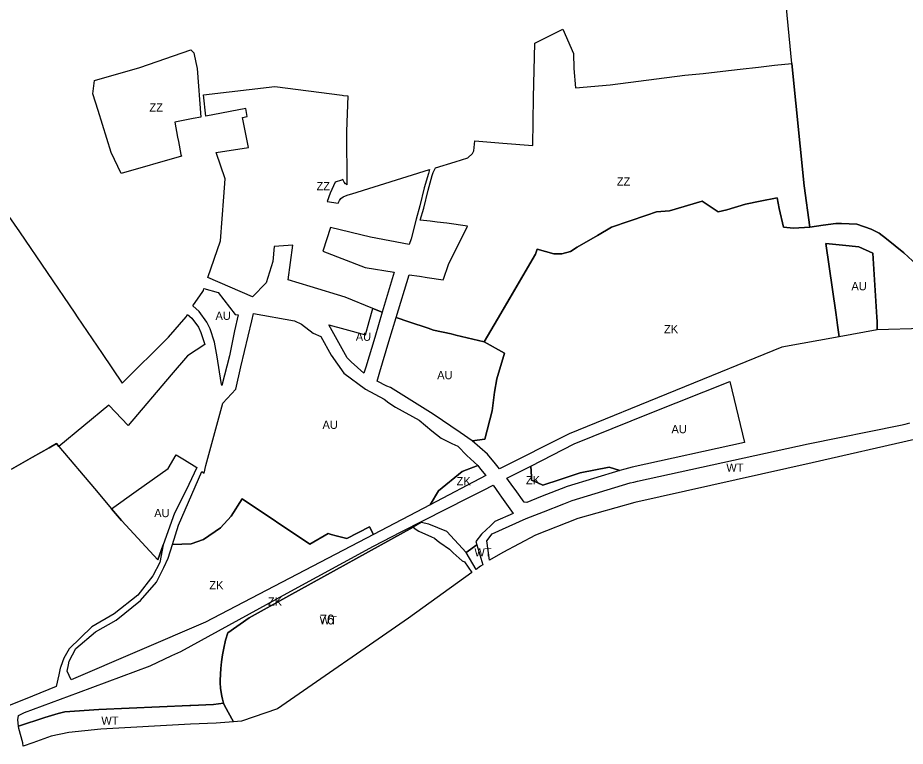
# Model space of a CAD drawing. Extents: x -535894 to -532834, y -1165802 to -1163647.
# Drawn here: x -534886 to -534347, y -1165569 to -1165127 of the extents above; entities that cross this region are included whole.
import ezdxf

# ---------------------------------------------------------------- set-up
doc = ezdxf.new("R2010")
doc.units = 0
for name, color, linetype in [('Vrstva 10', 7, 'Continuous'), ('Vrstva 16', 7, 'Continuous'), ('Vrstva 22', 7, 'Continuous'), ('Vrstva 4', 7, 'Continuous'), ('Vrstva 5', 7, 'Continuous'), ('Vrstva 61', 7, 'Continuous')]:
    doc.layers.add(name, color=color, linetype=linetype)

msp = doc.modelspace()

# ---------------------------------------------------------------- linework, layer by layer
at = {"layer": 'Vrstva 10'}
for points in [[(-534656.466, -1165308.487), (-534648.661, -1165282.513), (-534642.27, -1165283.46), (-534637.76, -1165284.12), (-534627.97, -1165285.63), (-534627.83, -1165285.22), (-534624.62, -1165276.23), (-534613.26, -1165253.08), (-534625.77, -1165251.25), (-534631.5, -1165250.59), (-534635.8, -1165250.1), (-534641.82, -1165249.4), (-534639.72, -1165242.1), (-534636.98, -1165231.14), (-534634.63, -1165222.23), (-534633.92, -1165220.53), (-534632.69, -1165217.6), (-534620.573, -1165213.915), (-534613.071, -1165211.633), (-534610.136, -1165208.971), (-534609.411, -1165207.236), (-534608.72, -1165201.29), (-534591.748, -1165202.638), (-534573.555, -1165204.082), (-534573.16, -1165174.91), (-534572.34, -1165142), (-534555.22, -1165133.48), (-534548.9, -1165148.28), (-534548.58, -1165157.34), (-534547.592, -1165169.021), (-534526.56, -1165167.24), (-534481.169, -1165161.423), (-534470.12, -1165160.31), (-534458.2, -1165158.95), (-534447.57, -1165157.79), (-534436.45, -1165156.54), (-534426.83, -1165155.34), (-534416.26, -1165154.3), (-534408.79, -1165228.57), (-534405.45, -1165253.73), (-534415.33, -1165254.24), (-534421.35, -1165253.74), (-534423.92, -1165242.4), (-534425.2, -1165235.77), (-534435.5, -1165237.88), (-534444.47, -1165239.8), (-534455.8, -1165243.06), (-534461.02, -1165244.38), (-534470.72, -1165237.94), (-534490.64, -1165243.85), (-534498.4, -1165244.45), (-534504.24, -1165246.32), (-534515.07, -1165249.99), (-534525.69, -1165253.61), (-534534.27, -1165258.67), (-534546.51, -1165265.89), (-534550.66, -1165268.35), (-534556, -1165269.92), (-534560.78, -1165269.82), (-534570.97, -1165266.95), (-534571.87, -1165270.05), (-534586.042, -1165294.326), (-534594.9, -1165309.5), (-534602.97, -1165323.34), (-534620.31, -1165319.14), (-534623.17, -1165318.51), (-534633.83, -1165316.18), (-534637.1, -1165315.06), (-534648.89, -1165311.07)], [(-534781.076, -1165145.96), (-534779.24, -1165147.77), (-534778.072, -1165153.706), (-534777.364, -1165157.303), (-534774.981, -1165186.877), (-534779.72, -1165187.79), (-534790.92, -1165189.96), (-534789.14, -1165199.14), (-534788.65, -1165201.64), (-534787.13, -1165209.49), (-534786.835, -1165210.52), (-534823.49, -1165221.01), (-534829.46, -1165208.31), (-534837.43, -1165182.94), (-534840.66, -1165172.65), (-534839.59, -1165164.67), (-534812.16, -1165156.7)], [(-534770.876, -1165284.164), (-534763.18, -1165261.89), (-534761.05, -1165235.16), (-534760.2, -1165224.39), (-534765.68, -1165208.38), (-534746.16, -1165205.31), (-534749.82, -1165187.09), (-534746.85, -1165186.52), (-534747.79, -1165181.61), (-534772.09, -1165186.32), (-534773.45, -1165173.38), (-534730.12, -1165168.22), (-534689.23, -1165173.62), (-534688.37, -1165173.69), (-534685.89, -1165173.92), (-534686.67, -1165195.7), (-534686.326, -1165227.952), (-534687.132, -1165227.394), (-534687.28, -1165227.291), (-534688.098, -1165226.32), (-534688.823, -1165224.816), (-534689.62, -1165225.087), (-534693.462, -1165226.393), (-534696.454, -1165232.948), (-534698.451, -1165238.101), (-534691.61, -1165239), (-534690.956, -1165237.548), (-534689.975, -1165236.279), (-534688.724, -1165235.276), (-534687.313, -1165234.607), (-534685.716, -1165234.065), (-534683.404, -1165233.352), (-534636.153, -1165218.674), (-534636.93, -1165221.04), (-534639.56, -1165229.81), (-534642.21, -1165240.82), (-534644.287, -1165248.754), (-534647.4, -1165260.65), (-534648.68, -1165264.17), (-534671.96, -1165259.81), (-534696.376, -1165253.853), (-534700.96, -1165268.14), (-534675.39, -1165278.09), (-534657.628, -1165281.081), (-534664.905, -1165305.299), (-534670.68, -1165302.976), (-534687.53, -1165296.2), (-534708.76, -1165289.69), (-534722.11, -1165285.6), (-534719.29, -1165264.53), (-534730.57, -1165265.33), (-534731.26, -1165274.58), (-534735.39, -1165287.4), (-534743.59, -1165295.91)]]:
    msp.add_lwpolyline(points, close=True, dxfattribs=at)
at = {"layer": 'Vrstva 16'}
for points in [[(-534336.76, -1165315.12), (-534364.57, -1165315.97), (-534364.596, -1165310.9), (-534364.61, -1165308.23), (-534367.17, -1165269.4), (-534375.67, -1165265.6), (-534385.585, -1165264.585), (-534395.69, -1165263.55), (-534389.63, -1165305.51), (-534388.99, -1165309.98), (-534388.62, -1165313.06), (-534387.514, -1165320.16), (-534422.4, -1165326.53), (-534551.38, -1165379.05), (-534593.742, -1165400.311), (-534597.026, -1165396.305), (-534598.221, -1165394.846), (-534601.042, -1165391.405), (-534610.247, -1165383.446), (-534602.56, -1165382.4), (-534598.25, -1165365.19), (-534596.74, -1165353.72), (-534595.37, -1165345.7), (-534590.76, -1165330.1), (-534602.97, -1165323.34), (-534594.9, -1165309.5), (-534571.87, -1165270.05), (-534570.97, -1165266.95), (-534560.78, -1165269.82), (-534556, -1165269.92), (-534550.66, -1165268.35), (-534546.51, -1165265.89), (-534534.27, -1165258.67), (-534525.69, -1165253.61), (-534515.07, -1165249.99), (-534504.24, -1165246.32), (-534498.4, -1165244.45), (-534490.64, -1165243.85), (-534470.72, -1165237.94), (-534461.02, -1165244.38), (-534455.8, -1165243.06), (-534444.47, -1165239.8), (-534435.5, -1165237.88), (-534425.2, -1165235.77), (-534423.92, -1165242.4), (-534421.35, -1165253.74), (-534415.33, -1165254.24), (-534405.45, -1165253.73), (-534397.29, -1165252.4), (-534389.65, -1165251.4), (-534386.06, -1165251.44), (-534376.79, -1165251.88), (-534368.13, -1165254.92), (-534363.2, -1165257.26), (-534358.8, -1165260.74), (-534348.28, -1165269.23), (-534340.36, -1165276.59)], [(-534889.94, -1165400.51), (-534885.71, -1165398.12), (-534877.22, -1165393.33), (-534867.2, -1165387.69), (-534862.73, -1165385.01), (-534861.21, -1165386.81), (-534839.653, -1165412.241), (-534829.214, -1165424.557), (-534823.21, -1165431.64), (-534822.96, -1165431.91), (-534801.16, -1165455.68), (-534797.86, -1165446.44), (-534800.02, -1165457.14), (-534804.19, -1165465.36), (-534813.3, -1165476.94), (-534827.72, -1165488.42), (-534841.13, -1165496.3), (-534854.91, -1165509.61), (-534858.15, -1165515.35), (-534858.97, -1165517.45), (-534860.3, -1165520.88), (-534860.51, -1165521.43), (-534861.32, -1165525.37), (-534862.8, -1165532.4), (-534877.24, -1165538.36), (-534912.68, -1165552.42)]]:
    msp.add_lwpolyline(points, dxfattribs=at)
for points in [[(-534607.004, -1165398.328), (-534605.192, -1165400.539), (-534601.98, -1165404.458), (-534635.941, -1165422.215), (-534630.7, -1165413.78), (-534616.38, -1165402.05)], [(-534520.704, -1165401.395), (-534552.702, -1165410.995), (-534568.837, -1165417.43), (-534577.132, -1165420.742), (-534578.843, -1165420.532), (-534584.327, -1165412.961), (-534585.708, -1165411.053), (-534589.332, -1165406.049), (-534574.828, -1165398.663), (-534574.43, -1165404.96), (-534574.28, -1165407.33), (-534570.57, -1165408.93), (-534567.43, -1165410.29), (-534557.01, -1165406.86), (-534544.87, -1165402.87), (-534527.22, -1165399.28)], [(-534625.805, -1165438.391), (-534636.67, -1165433.924), (-534641.319, -1165433.008), (-534646.155, -1165435.684), (-534721.707, -1165477.481), (-534745.62, -1165490.71), (-534758.745, -1165499.805), (-534759.99, -1165504.33), (-534761.08, -1165509.14), (-534761.82, -1165513.22), (-534762.44, -1165517.45), (-534762.85, -1165521.52), (-534763.11, -1165525.02), (-534763.25, -1165528.91), (-534763.26, -1165530.29), (-534763.09, -1165533.48), (-534762.76, -1165536.1), (-534762.37, -1165538.34), (-534761.95, -1165540.22), (-534761.238, -1165542.687), (-534767.34, -1165543.34), (-534781.05, -1165543.94), (-534781.63, -1165543.97), (-534836.88, -1165546.52), (-534857.57, -1165547.81), (-534861.62, -1165548.94), (-534869.82, -1165551.23), (-534885.69, -1165556.54), (-534886.11, -1165552.64), (-534885.76, -1165550.05), (-534882.03, -1165548.34), (-534849.32, -1165536.17), (-534805.71, -1165519.94), (-534792.57, -1165513.75), (-534787.1, -1165511.18), (-534722.56, -1165475.88), (-534670.22, -1165447.23), (-534653.44, -1165438.69), (-534612.41, -1165417.8), (-534603.53, -1165413.28), (-534597.581, -1165410.25), (-534593.887, -1165415.471), (-534592.444, -1165417.51), (-534585.468, -1165427.37), (-534596.584, -1165432.419), (-534599.518, -1165435.213), (-534601.568, -1165437.166), (-534604.649, -1165440.099), (-534608.122, -1165444.506), (-534607.549, -1165446.401), (-534614.062, -1165451.061)], [(-534792.243, -1165446.224), (-534780.95, -1165445.79), (-534773.45, -1165443.33), (-534763.2, -1165436.26), (-534756.71, -1165429.04), (-534749.861, -1165418.525), (-534708.8, -1165446.03), (-534697.82, -1165439.67), (-534696.005, -1165440.161), (-534692.969, -1165440.982), (-534686.509, -1165442.728), (-534672.71, -1165435.57), (-534670.299, -1165440.18), (-534772.12, -1165493.42), (-534853.75, -1165528.43), (-534856.09, -1165523.12), (-534855.37, -1165519.3), (-534854.95, -1165517.06), (-534850.87, -1165509.4), (-534839.06, -1165499.27), (-534826.42, -1165492.24), (-534811.76, -1165480.33), (-534801.92, -1165469.07), (-534797.58, -1165460.25), (-534794.8, -1165454.57)]]:
    msp.add_lwpolyline(points, close=True, dxfattribs=at)
at = {"layer": 'Vrstva 22'}
for points in [[(-534340.36, -1165276.59), (-534348.28, -1165269.23), (-534358.8, -1165260.74), (-534363.2, -1165257.26), (-534368.13, -1165254.92), (-534376.79, -1165251.88), (-534386.06, -1165251.44), (-534389.65, -1165251.4), (-534397.29, -1165252.4), (-534405.45, -1165253.73), (-534408.79, -1165228.57), (-534416.26, -1165154.3), (-534420.23, -1165114.18), (-534421.45, -1165101.43), (-534422.065, -1165096.672), (-534422.065, -1165096.672), (-534403.258, -1165095.841), (-534381.169, -1165094.484), (-534372.898, -1165093.976), (-534362.94, -1165093.25), (-534340.945, -1165094.96)], [(-534899.65, -1165235.85), (-534885.09, -1165256.54), (-534851.51, -1165305.91), (-534850.05, -1165308.06), (-534834.92, -1165330.4), (-534822.71, -1165348.42), (-534794.69, -1165320.4), (-534784.03, -1165308.09), (-534783.149, -1165306.655), (-534780.557, -1165308.993), (-534776.549, -1165314.45), (-534774.961, -1165317.626), (-534772.56, -1165324.913), (-534783.217, -1165331.674), (-534793.03, -1165343.33), (-534819.26, -1165374.14), (-534830.8, -1165361.69), (-534861.21, -1165386.81), (-534862.73, -1165385.01), (-534867.2, -1165387.69), (-534877.22, -1165393.33), (-534885.71, -1165398.12), (-534889.94, -1165400.51)]]:
    msp.add_lwpolyline(points, dxfattribs=at)
for points in [[(-534364.57, -1165315.97), (-534387.514, -1165320.16), (-534388.62, -1165313.06), (-534388.99, -1165309.98), (-534389.63, -1165305.51), (-534395.69, -1165263.55), (-534385.585, -1165264.585), (-534375.67, -1165265.6), (-534367.17, -1165269.4), (-534364.61, -1165308.23), (-534364.596, -1165310.9)], [(-534762.608, -1165347.87), (-534765.202, -1165332.461), (-534766.72, -1165323.467), (-534769.399, -1165315.334), (-534771.411, -1165311.31), (-534776.083, -1165304.947), (-534779.821, -1165301.364), (-534779.49, -1165300.88), (-534774.33, -1165293.32), (-534773.48, -1165292.09), (-534773.21, -1165290.92), (-534764.53, -1165293.41), (-534754.18, -1165306.73), (-534752.459, -1165306.87), (-534754.687, -1165316.58), (-534757.69, -1165331.84), (-534762.293, -1165349.741)], [(-534607.004, -1165398.328), (-534616.38, -1165402.05), (-534630.7, -1165413.78), (-534635.941, -1165422.215), (-534670.299, -1165440.18), (-534672.71, -1165435.57), (-534686.509, -1165442.728), (-534692.969, -1165440.982), (-534696.005, -1165440.161), (-534697.82, -1165439.67), (-534708.8, -1165446.03), (-534749.861, -1165418.525), (-534756.71, -1165429.04), (-534763.2, -1165436.26), (-534773.45, -1165443.33), (-534780.95, -1165445.79), (-534792.243, -1165446.224), (-534788.69, -1165434.63), (-534774.44, -1165402.06), (-534773.095, -1165402.961), (-534772.095, -1165398.401), (-534761.79, -1165360.41), (-534753.851, -1165351.984), (-534750.684, -1165338.491), (-534744.129, -1165310.569), (-534743.052, -1165305.979), (-534718.125, -1165310.44), (-534714.037, -1165312.461), (-534706.875, -1165318.091), (-534702.167, -1165320.064), (-534695.88, -1165331.28), (-534688.17, -1165342.38), (-534675.04, -1165351.98), (-534663.67, -1165357.97), (-534660.93, -1165360.38), (-534656.806, -1165362.855), (-534642.55, -1165370.754), (-534634.894, -1165377.362), (-534629.25, -1165381.75), (-534622.61, -1165384.94), (-534619.01, -1165386.65), (-534613.509, -1165392.332)], [(-534670.68, -1165302.976), (-534664.905, -1165305.299), (-534669.517, -1165320.647), (-534674.897, -1165338.553), (-534676.018, -1165342.285), (-534683.831, -1165335.456), (-534686.218, -1165332.95), (-534697.266, -1165312.904), (-534687.7, -1165315.57), (-534675.18, -1165319.07), (-534672.89, -1165310.88)], [(-534602.97, -1165323.34), (-534590.76, -1165330.1), (-534595.37, -1165345.7), (-534596.74, -1165353.72), (-534598.25, -1165365.19), (-534602.56, -1165382.4), (-534610.247, -1165383.446), (-534617.669, -1165378.227), (-534633.99, -1165367.14), (-534659.903, -1165351.067), (-534662.084, -1165350.114), (-534668.097, -1165347.197), (-534666.386, -1165341.503), (-534660.844, -1165323.061), (-534656.466, -1165308.487), (-534648.89, -1165311.07), (-534637.1, -1165315.06), (-534633.83, -1165316.18), (-534623.17, -1165318.51), (-534620.31, -1165319.14)], [(-534544.87, -1165402.87), (-534557.01, -1165406.86), (-534567.43, -1165410.29), (-534570.57, -1165408.93), (-534574.28, -1165407.33), (-534574.43, -1165404.96), (-534574.828, -1165398.663), (-534548.51, -1165385.26), (-534502.24, -1165366.65), (-534454.003, -1165347.255), (-534444.988, -1165384.388), (-534513.151, -1165399.411), (-534517.583, -1165400.459), (-534520.704, -1165401.395), (-534527.22, -1165399.28)], [(-534829.214, -1165424.557), (-534814.32, -1165413.92), (-534794.94, -1165400.08), (-534790.12, -1165391.9), (-534784.89, -1165394.84), (-534777.48, -1165399.64), (-534783.92, -1165413.27), (-534791.04, -1165427.36), (-534797.86, -1165446.44), (-534801.16, -1165455.68), (-534822.96, -1165431.91), (-534823.21, -1165431.64)]]:
    msp.add_lwpolyline(points, close=True, dxfattribs=at)
at = {"layer": 'Vrstva 4'}
msp.add_lwpolyline([(-534341.94, -1165382.62), (-534404.04, -1165396.72), (-534511.63, -1165420.88), (-534546.3, -1165430.52), (-534571.82, -1165440.57), (-534591.82, -1165451.2), (-534599.87, -1165455.71), (-534601.363, -1165444.1), (-534598.29, -1165439.76), (-534577.5, -1165430.58), (-534567.01, -1165426.39), (-534554.75, -1165421.51), (-534549.73, -1165419.5), (-534514.4, -1165408.9), (-534512.18, -1165408.41), (-534509.97, -1165407.93), (-534406.37, -1165385.09), (-534350.42, -1165373.76), (-534347.57, -1165373.21), (-534344.67, -1165372.49)], dxfattribs=at)
for points in [[(-534607.908, -1165461.42), (-534614.062, -1165451.061), (-534607.549, -1165446.401), (-534603.882, -1165458.535), (-534605.28, -1165459.52)], [(-534855.2, -1165560.47), (-534865.99, -1165562.72), (-534877.129, -1165566.697), (-534882.85, -1165568.74), (-534883.19, -1165566.76), (-534885.55, -1165558), (-534885.69, -1165556.54), (-534869.82, -1165551.23), (-534861.62, -1165548.94), (-534857.57, -1165547.81), (-534836.88, -1165546.52), (-534781.63, -1165543.97), (-534781.05, -1165543.94), (-534767.34, -1165543.34), (-534761.238, -1165542.687), (-534760.77, -1165544.08), (-534755.168, -1165553.95), (-534765.78, -1165554.79), (-534781.3, -1165555.36), (-534835.68, -1165558.38)]]:
    msp.add_lwpolyline(points, close=True, dxfattribs=at)
at = {"layer": 'Vrstva 5'}
msp.add_lwpolyline([(-534646.155, -1165435.684), (-534644.3, -1165437.19), (-534642.65, -1165438.14), (-534635.1, -1165441.55), (-534633.13, -1165442.51), (-534631.5, -1165443.83), (-534629.91, -1165445), (-534624.12, -1165449.21), (-534621.78, -1165451.3), (-534616.51, -1165456.28), (-534614.92, -1165456.72), (-534610.461, -1165463.267), (-534648.91, -1165491.07), (-534728.46, -1165546.03), (-534750.37, -1165553.57), (-534755.168, -1165553.95), (-534760.77, -1165544.08), (-534761.238, -1165542.687), (-534761.95, -1165540.22), (-534762.37, -1165538.34), (-534762.76, -1165536.1), (-534763.09, -1165533.48), (-534763.26, -1165530.29), (-534763.25, -1165528.91), (-534763.11, -1165525.02), (-534762.85, -1165521.52), (-534762.44, -1165517.45), (-534761.82, -1165513.22), (-534761.08, -1165509.14), (-534759.99, -1165504.33), (-534758.745, -1165499.805), (-534745.62, -1165490.71), (-534721.707, -1165477.481)], close=True, dxfattribs=at)

# ---------------------------------------------------------------- texts
at = {"layer": 'Vrstva 10'}
for rotation, p in [(0, (-534806.2566, -1165183.485)), (360, (-534704.8015, -1165231.2337)), (360, (-534522.533, -1165228.41))]:
    msp.add_text('ZZ', height=5, rotation=rotation, dxfattribs=at).set_placement(p)
at = {"layer": 'Vrstva 16'}
for rotation, p in [(0, (-534493.862, -1165318.0405)), (360, (-534577.7362, -1165409.7025)), (0, (-534619.7577, -1165410.2715)), (360, (-534769.8759, -1165473.4775)), (0, (-534734.3486, -1165483.395))]:
    msp.add_text('ZK', height=5, rotation=rotation, dxfattribs=at).set_placement(p)
at = {"layer": 'Vrstva 22'}
for rotation, p in [(0, (-534380.13, -1165291.9775)), (0, (-534766.14, -1165309.9258)), (0, (-534681.0092, -1165322.6305)), (360, (-534631.5714, -1165345.9665)), (360, (-534701.2004, -1165376.1015)), (0, (-534489.3657, -1165378.7725)), (0, (-534803.347, -1165429.6896))]:
    msp.add_text('AU', height=5, rotation=rotation, dxfattribs=at).set_placement(p)
at = {"layer": 'Vrstva 4'}
for p in [(-534456.0542, -1165402.165), (-534608.972, -1165453.5241), (-534835.4426, -1165555.7135)]:
    msp.add_text('WT', height=5, rotation=0, dxfattribs=at).set_placement(p)
at = {"layer": 'Vrstva 5'}
msp.add_text('WT', height=5, rotation=0, dxfattribs=at).set_placement((-534702.9401, -1165494.817))
at = {"layer": 'Vrstva 61'}
msp.add_text('76', height=6, rotation=360, dxfattribs=at).set_placement((-534702.9401, -1165494.817))

doc.saveas('drawing.dxf')
